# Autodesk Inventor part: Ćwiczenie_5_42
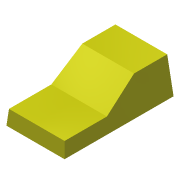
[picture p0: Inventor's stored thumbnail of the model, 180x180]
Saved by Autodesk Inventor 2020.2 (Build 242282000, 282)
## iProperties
Created: 2005-04
Part Number: Ćwiczenie_5_42
Document SubType Name: Modeling
Designer: F.Stasiak
Manufacturer: Standard
Standards Organization: Custom
Density: 1 g/cm^3
Material: Ogólny
Appearance: Gładki - żółty
Manager: www.cadconsulting.pl
Company: Fabian Stasiak CAD Consulting
Author: F.Stasiak
Subject: Zbiór ćwiczeń. Autodesk Inventor 2020. Kurs podstawowy
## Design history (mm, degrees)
node "Szkic1"
sketch "Szkic2"
  geometry: L1 (-37.5, 10)-(-37.5, 0); L2 (-37.5, 0)-(37.5, 0); L3 (37.5, 0)-(37.5, 25); L4 (37.5, 25)-(12.5, 25); L5 (12.5, 25)-(-7.5, 10); L6 (-7.5, 10)-(-37.5, 10); 2 further points
  constraints: 12 end point, 3 parallel, 1 coincident, 1 midpoint, 1 perpendicular, 1 vertical
  dimensions: "d0" = 75 distance of L1.end L2.end; "d1" = 25 distance of L2.end L3.end; "d2" = 10 distance of L1.start L1.end; "d3" = 25 distance of L3.end L4.end; "d4" = 30 distance of L5.end L1.start
extrude "Wyciągnięcie proste1" new body sketch "Szkic2" stored distance "d5" = 40; taper "d6" = 0 deg
feature "Szkic powierzchni1" dims angle "d22" = 5 deg
node "Bryła1"
node "Korpusy bryłowe"
node "Korpusy powierzchniowe"
